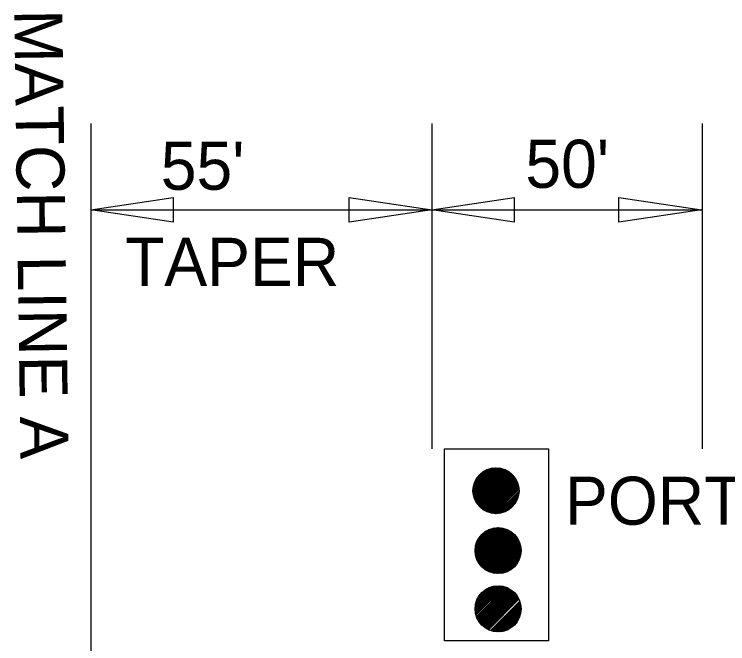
# Model space of a CAD drawing. Extents: x 1398460 to 1408037, y 380768 to 383968.
# Drawn here: x 1399480.3 to 1399569.4, y 382266.3 to 382344.9 of the extents above; entities that cross this region are included whole.
import ezdxf

# ---------------------------------------------------------------- set-up
doc = ezdxf.new("R2010")
doc.units = 0
doc.layers.add('Default', color=7, linetype='Continuous')

msp = doc.modelspace()

# ---------------------------------------------------------------- linework, layer by layer
at = {"layer": 'Default'}
for p, q in [((1399489.848, 382331.274), (1399489.848, 382270.925)), ((1399532.417, 382331.274), (1399532.417, 382290.639)), ((1399566.198, 382331.274), (1399566.198, 382290.639)), ((1399489.848, 382320.488), (1399500.151, 382322.035)), ((1399500.151, 382322.035), (1399500.151, 382318.941)), ((1399522.113, 382318.941), (1399522.113, 382322.035)), ((1399522.113, 382322.035), (1399532.417, 382320.488)), ((1399532.417, 382320.488), (1399542.72, 382322.035)), ((1399542.72, 382322.035), (1399542.72, 382318.941)), ((1399555.783, 382318.941), (1399555.783, 382322.035)), ((1399555.783, 382322.035), (1399566.087, 382320.488)), ((1399500.151, 382318.941), (1399489.848, 382320.488)), ((1399489.848, 382320.488), (1399532.417, 382320.488)), ((1399532.417, 382320.488), (1399522.113, 382318.941)), ((1399532.417, 382320.488), (1399566.087, 382320.488)), ((1399542.72, 382318.941), (1399532.417, 382320.488)), ((1399566.087, 382320.488), (1399555.783, 382318.941)), ((1399489.848, 382295.775), (1399489.848, 382244.742)), ((1399537.569, 382285.449), (1399540.402, 382288.282)), ((1399537.572, 382285.275), (1399540.576, 382288.28)), ((1399537.578, 382285.635), (1399540.217, 382288.274)), ((1399537.584, 382285.111), (1399540.741, 382288.267)), ((1399537.601, 382285.834), (1399540.017, 382288.251)), ((1399537.605, 382284.955), (1399540.897, 382288.247)), ((1399537.633, 382284.806), (1399541.046, 382288.219)), ((1399537.642, 382286.053), (1399539.799, 382288.209)), ((1399537.667, 382284.663), (1399541.188, 382288.184)), ((1399537.707, 382284.527), (1399541.325, 382288.144)), ((1399537.71, 382286.297), (1399539.554, 382288.142)), ((1399537.753, 382284.396), (1399541.456, 382288.099)), ((1399537.804, 382284.27), (1399541.582, 382288.048)), ((1399537.821, 382286.585), (1399539.267, 382288.031)), ((1399537.859, 382284.148), (1399541.703, 382287.992)), ((1399537.92, 382284.032), (1399541.82, 382287.932)), ((1399537.984, 382283.92), (1399541.932, 382287.867)), ((1399538.033, 382286.973), (1399538.878, 382287.819)), ((1399538.053, 382283.812), (1399542.04, 382287.799)), ((1399538.126, 382283.708), (1399542.144, 382287.726)), ((1399538.202, 382283.608), (1399542.244, 382287.649)), ((1399538.283, 382283.511), (1399542.34, 382287.568)), ((1399538.368, 382283.419), (1399542.432, 382287.484)), ((1399538.456, 382283.331), (1399542.521, 382287.395)), ((1399538.548, 382283.246), (1399542.605, 382287.303)), ((1399538.644, 382283.166), (1399542.686, 382287.207)), ((1399538.744, 382283.089), (1399542.763, 382287.107)), ((1399538.848, 382283.016), (1399542.835, 382287.003)), ((1399538.957, 382282.947), (1399542.904, 382286.895)), ((1399539.069, 382282.883), (1399542.968, 382286.783)), ((1399539.185, 382282.823), (1399543.029, 382286.666)), ((1399539.307, 382282.767), (1399543.084, 382286.545)), ((1399539.433, 382282.717), (1399543.135, 382286.419)), ((1399539.564, 382282.671), (1399543.181, 382286.288)), ((1399539.7, 382282.631), (1399543.221, 382286.151)), ((1399539.843, 382282.596), (1399543.255, 382286.009)), ((1399539.992, 382282.569), (1399543.283, 382285.86)), ((1399540.148, 382282.548), (1399543.303, 382285.703)), ((1399540.313, 382282.536), (1399543.316, 382285.539)), ((1399540.487, 382282.533), (1399543.318, 382285.365)), ((1399540.672, 382282.542), (1399543.309, 382285.179)), ((1399540.872, 382282.565), (1399543.286, 382284.979)), ((1399541.091, 382282.607), (1399543.245, 382284.761)), ((1399541.335, 382282.675), (1399543.177, 382284.516)), ((1399541.624, 382282.786), (1399543.065, 382284.228)), ((1399542.014, 382282.999), (1399542.852, 382283.838)), ((1399537.832, 382277.964), (1399540.665, 382280.797)), ((1399537.835, 382277.79), (1399540.839, 382280.794)), ((1399537.841, 382278.15), (1399540.48, 382280.789)), ((1399537.848, 382277.626), (1399541.004, 382280.782)), ((1399537.864, 382278.349), (1399540.28, 382280.766)), ((1399537.868, 382277.47), (1399541.16, 382280.762)), ((1399537.896, 382277.321), (1399541.309, 382280.734)), ((1399537.905, 382278.567), (1399540.062, 382280.724)), ((1399537.93, 382277.178), (1399541.452, 382280.699)), ((1399537.971, 382277.042), (1399541.588, 382280.659)), ((1399537.973, 382278.812), (1399539.818, 382280.656)), ((1399538.016, 382276.911), (1399541.719, 382280.613)), ((1399538.067, 382276.785), (1399541.845, 382280.563)), ((1399538.084, 382279.1), (1399539.53, 382280.545)), ((1399538.123, 382276.663), (1399541.966, 382280.507)), ((1399538.183, 382276.547), (1399542.083, 382280.447)), ((1399538.247, 382276.435), (1399542.195, 382280.382)), ((1399538.296, 382279.488), (1399539.141, 382280.334)), ((1399538.316, 382276.326), (1399542.303, 382280.314)), ((1399538.389, 382276.222), (1399542.407, 382280.241)), ((1399538.466, 382276.122), (1399542.507, 382280.164)), ((1399538.546, 382276.026), (1399542.603, 382280.083)), ((1399538.631, 382275.934), (1399542.696, 382279.999)), ((1399538.719, 382275.846), (1399542.784, 382279.91)), ((1399538.811, 382275.761), (1399542.868, 382279.818)), ((1399538.908, 382275.681), (1399542.949, 382279.722)), ((1399539.008, 382275.604), (1399543.026, 382279.622)), ((1399539.112, 382275.531), (1399543.099, 382279.518)), ((1399539.22, 382275.462), (1399543.167, 382279.41)), ((1399539.332, 382275.398), (1399543.232, 382279.298)), ((1399539.449, 382275.338), (1399543.292, 382279.181)), ((1399539.57, 382275.282), (1399543.347, 382279.06)), ((1399539.696, 382275.231), (1399543.398, 382278.934)), ((1399539.827, 382275.186), (1399543.444, 382278.803)), ((1399539.964, 382275.146), (1399543.484, 382278.666)), ((1399540.106, 382275.111), (1399543.518, 382278.524)), ((1399540.255, 382275.084), (1399543.546, 382278.375)), ((1399540.411, 382275.063), (1399543.567, 382278.218)), ((1399540.576, 382275.051), (1399543.579, 382278.054)), ((1399540.75, 382275.048), (1399543.581, 382277.88)), ((1399540.936, 382275.057), (1399543.573, 382277.694)), ((1399541.135, 382275.08), (1399543.55, 382277.494)), ((1399541.354, 382275.122), (1399543.508, 382277.276)), ((1399541.599, 382275.19), (1399543.44, 382277.031)), ((1399541.887, 382275.301), (1399543.328, 382276.743)), ((1399542.277, 382275.514), (1399543.115, 382276.353)), ((1399537.832, 382270.616), (1399540.744, 382273.527)), ((1399537.836, 382270.796), (1399540.564, 382273.524)), ((1399537.84, 382270.446), (1399540.913, 382273.52)), ((1399537.852, 382270.989), (1399540.371, 382273.508)), ((1399537.856, 382270.286), (1399541.074, 382273.504)), ((1399537.88, 382270.133), (1399541.227, 382273.48)), ((1399537.884, 382271.198), (1399540.161, 382273.475)), ((1399537.91, 382269.987), (1399541.373, 382273.449)), ((1399537.939, 382271.43), (1399539.93, 382273.421)), ((1399537.947, 382269.847), (1399541.513, 382273.412)), ((1399537.99, 382269.713), (1399541.647, 382273.37)), ((1399538.028, 382271.695), (1399539.664, 382273.332)), ((1399538.038, 382269.584), (1399541.776, 382273.322)), ((1399538.091, 382269.46), (1399541.899, 382273.269)), ((1399538.149, 382269.341), (1399542.018, 382273.211)), ((1399538.181, 382272.025), (1399539.335, 382273.179)), ((1399538.211, 382269.227), (1399542.133, 382273.149)), ((1399538.277, 382269.116), (1399542.244, 382273.082)), ((1399538.348, 382269.01), (1399542.35, 382273.012)), ((1399538.422, 382268.908), (1399542.452, 382272.937)), ((1399538.501, 382268.809), (1399542.55, 382272.859)), ((1399538.583, 382268.715), (1399542.645, 382272.776)), ((1399538.67, 382268.625), (1399542.735, 382272.69)), ((1399538.76, 382268.538), (1399542.822, 382272.6)), ((1399538.854, 382268.455), (1399542.905, 382272.506)), ((1399538.951, 382268.376), (1399542.984, 382272.408)), ((1399539.053, 382268.301), (1399543.059, 382272.306)), ((1399539.159, 382268.23), (1399543.129, 382272.201)), ((1399539.269, 382268.163), (1399543.196, 382272.091)), ((1399539.383, 382268.101), (1399543.259, 382271.976)), ((1399539.502, 382268.043), (1399543.317, 382271.858)), ((1399539.753, 382267.941), (1399543.419, 382271.606)), ((1399539.887, 382267.897), (1399543.462, 382271.473)), ((1399540.026, 382267.86), (1399543.5, 382271.334)), ((1399540.171, 382267.828), (1399543.531, 382271.188)), ((1399540.323, 382267.804), (1399543.556, 382271.036)), ((1399540.483, 382267.787), (1399543.573, 382270.876)), ((1399540.652, 382267.778), (1399543.581, 382270.708)), ((1399540.831, 382267.781), (1399543.579, 382270.529)), ((1399541.022, 382267.795), (1399543.564, 382270.338)), ((1399541.229, 382267.826), (1399543.534, 382270.13)), ((1399541.458, 382267.878), (1399543.482, 382269.901)), ((1399541.719, 382267.962), (1399543.398, 382269.64)), ((1399542.039, 382268.105), (1399543.254, 382269.32)), ((1399542.599, 382268.489), (1399542.871, 382268.76))]:
    msp.add_line(p, q, dxfattribs=at)
msp.add_lwpolyline([(1399534.017, 382290.639), (1399547.008, 382290.639), (1399547.008, 382266.662), (1399534.017, 382266.662)], close=True, dxfattribs=at)
for centre in [(1399540.444, 382285.408), (1399540.707, 382277.923), (1399540.707, 382270.653)]:
    msp.add_circle(centre, 2.875, dxfattribs=at)

# ---------------------------------------------------------------- texts
msp.add_text('MATCH LINE A', height=6, rotation=270.80593, dxfattribs=at).set_placement((1399480.279, 382345.487))
for s, p in [("  55' ", (1399494.124, 382322.994)), ("50'", (1399544.111, 382323.236)), ('TAPER', (1399494.124, 382310.994)), ('PORTABLE TRAFFIC SIGNAL SYSTEM', (1399549.057, 382281.154))]:
    msp.add_text(s, height=6, dxfattribs=at).set_placement(p)

doc.saveas('drawing.dxf')
